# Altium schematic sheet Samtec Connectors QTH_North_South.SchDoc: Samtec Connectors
size A3; Date: 01-DEC-2013; CompanyName: STMicroelectronics; Organization: Microcontrollers Division; Address1: 12, Rue Jules HOROWITZ; Address2: 38019 Grenoble; Address3: FRANCE; DocumentNumber: MB1263; Revision: C-04; SheetNumber: 6; SheetTotal: 11; Project: STM32MP157-EVAL; PageSetup: Record=PageOptions¦CenterHorizontal=True¦CenterVertical=True¦PrintScale=1.00¦XCorrection=1.00¦YCorrection=1.00¦PrintKind=1¦BorderSize=5000000¦LeftOffset=0¦BottomOffset=0¦Orientation=2¦PaperLength=1000¦PaperWidth=1000¦Scale=100¦PaperSource=7¦PrintQuality=-3¦MediaType=1¦DitherType=10¦PrintScaleMode=1¦PaperKind=A3¦PaperIndex=8
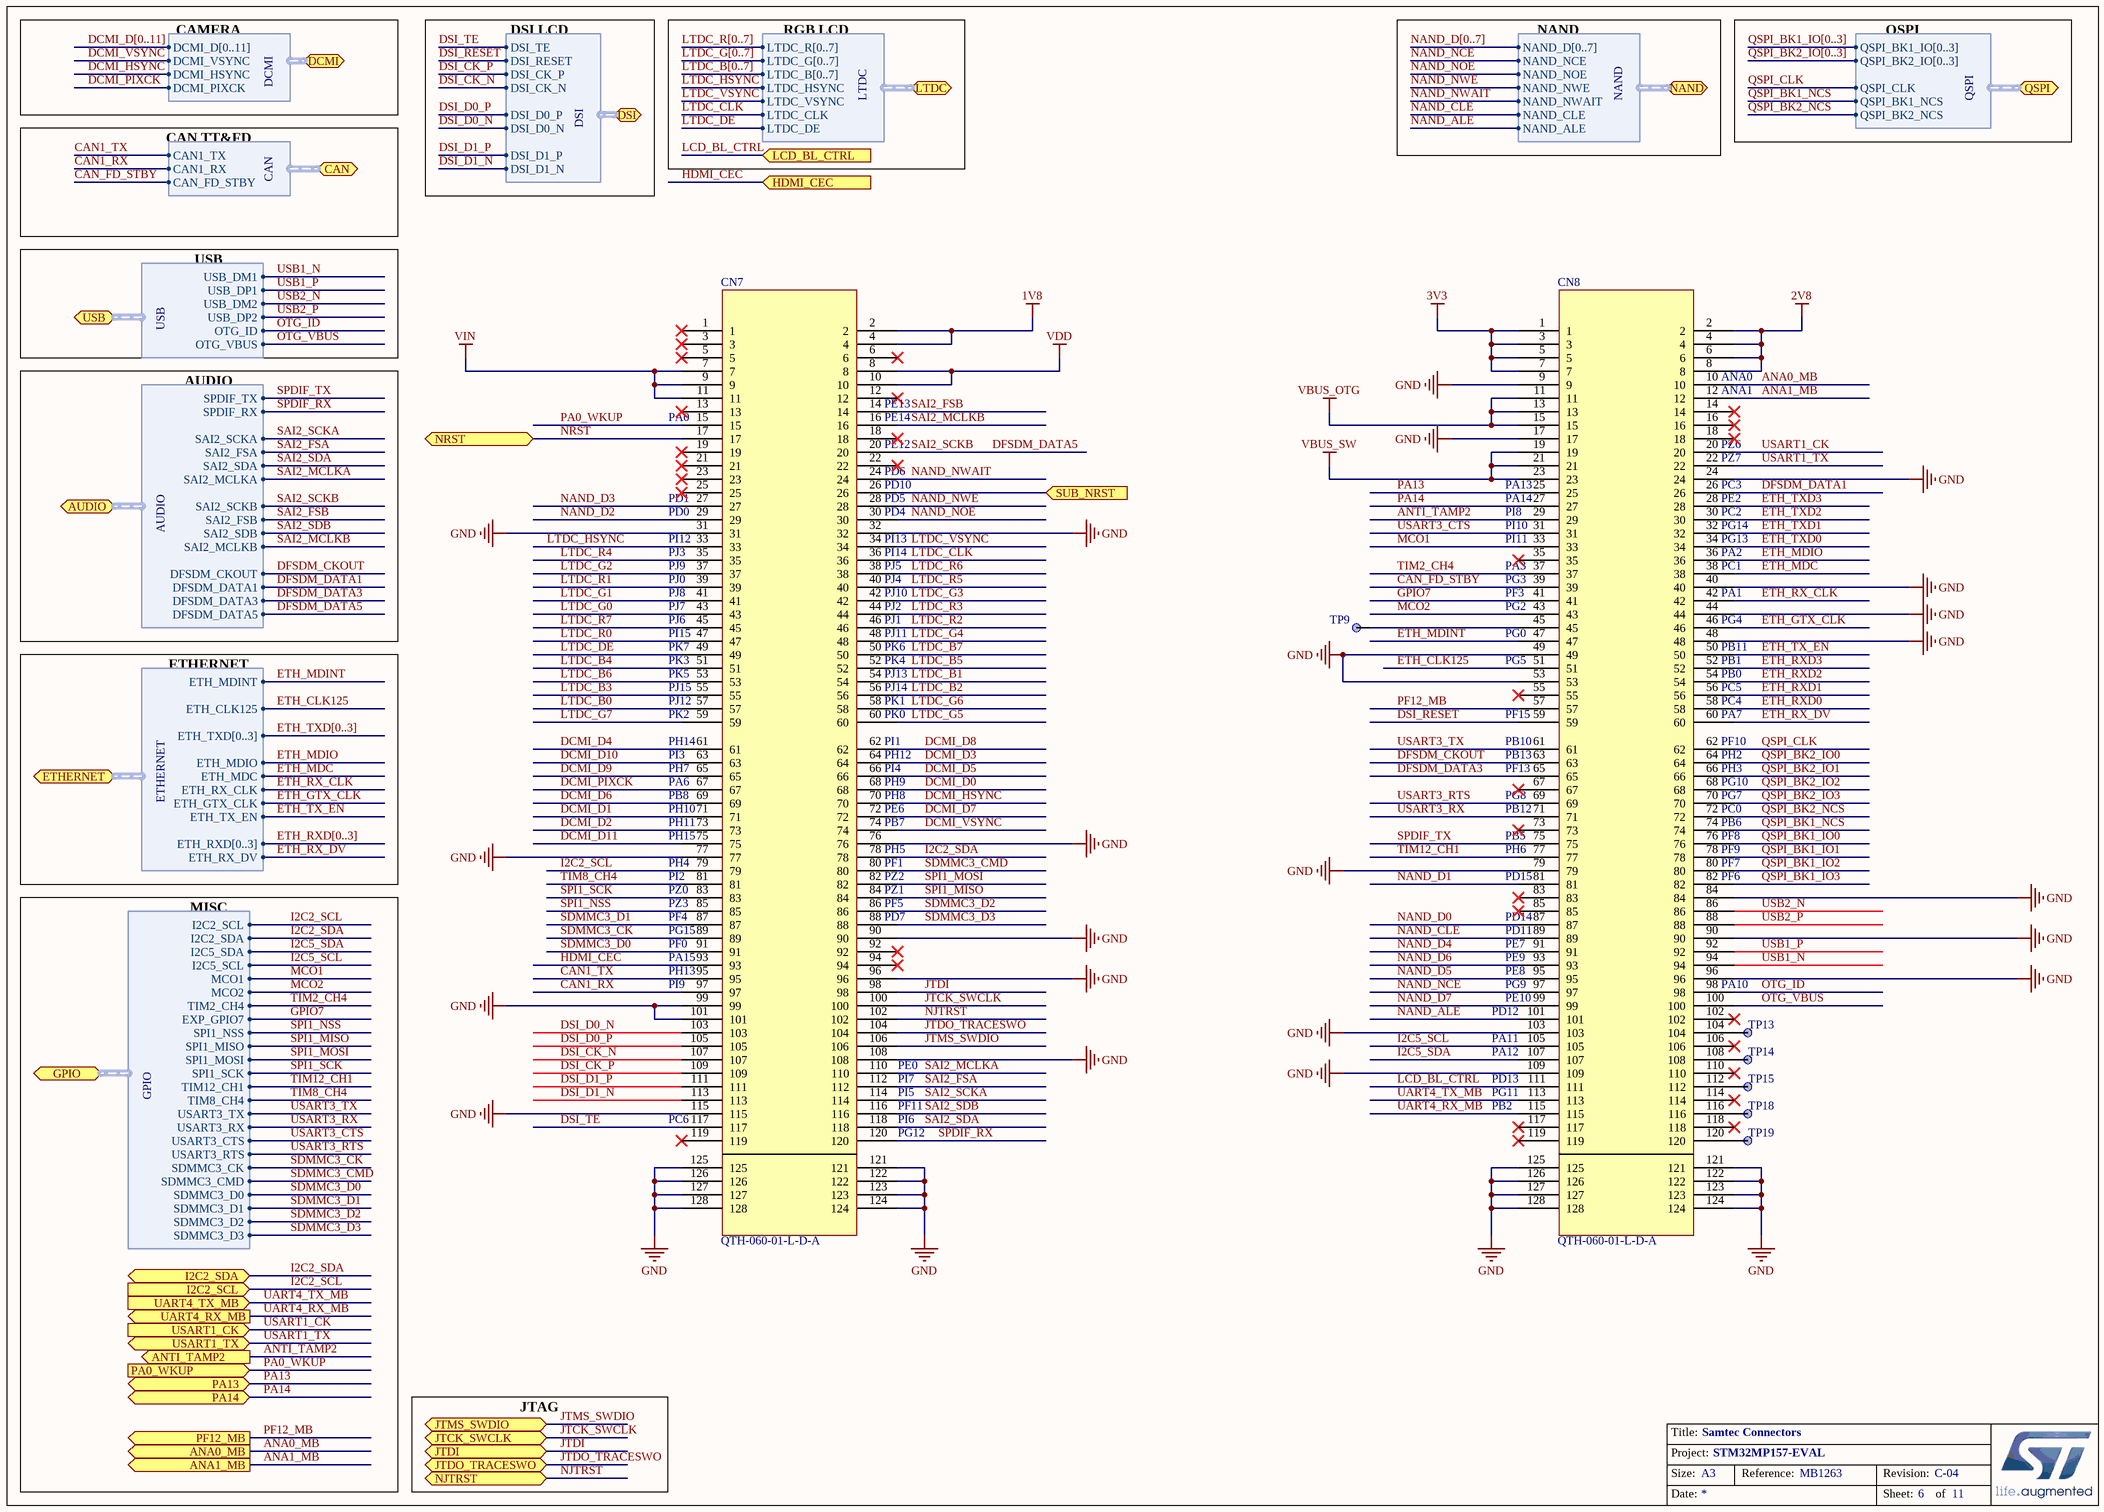
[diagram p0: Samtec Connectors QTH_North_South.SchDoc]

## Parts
CN7  QTH-060-01-L-D-A  [CON_SAMTEC_QTH-060-01-L-D-A]
CN8  QTH-060-01-L-D-A  [CON_SAMTEC_QTH-060-01-L-D-A]
TP9  TP  [TP_SMD_1MM]  (value not drawn)  (no BOM)
TP13  TP  [TP_SMD_1MM]  (value not drawn)  (no BOM)
TP14  TP  [TP_SMD_1MM]  (value not drawn)  (no BOM)
TP15  TP  [TP_SMD_1MM]  (value not drawn)  (no BOM)
TP18  TP  [TP_SMD_1MM]  (value not drawn)  (no BOM)
TP19  TP  [TP_SMD_1MM]  (value not drawn)  (no BOM)

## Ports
ANA0_MB (out), ANA1_MB (out), ANTI_TAMP2 (out), AUDIO (harness AUDIO), CAN (harness CAN), DCMI (harness DCMI), DSI (harness DSI), ETHERNET (harness ETHERNET), GPIO (harness GPIO), HDMI_CEC (in), I2C2_SCL (in), I2C2_SDA (bidir), JTCK_SWCLK, JTDI, JTDO_TRACESWO, JTMS_SWDIO, LCD_BL_CTRL (in), LTDC (harness LTDC), NAND (harness NAND), NJTRST, NRST (bidir), PA0_WKUP (in), PA13, PA14, PF12_MB (out), QSPI (harness QSPI), SUB_NRST (in), UART4_RX_MB (out), UART4_TX_MB (in), USART1_CK (in), USART1_TX (bidir), USB (harness USB)

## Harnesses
NAND: NAND_D[0..7], NAND_NCE, NAND_NOE, NAND_NWE, NAND_NWAIT, NAND_CLE, NAND_ALE
QSPI: QSPI_BK1_IO[0..3], QSPI_BK2_IO[0..3], QSPI_CLK, QSPI_BK1_NCS, QSPI_BK2_NCS
DSI: DSI_CK_P, DSI_CK_N, DSI_D0_P, DSI_D0_N, DSI_D1_P, DSI_D1_N, DSI_TE, DSI_RESET
LTDC: LTDC_R[0..7], LTDC_G[0..7], LTDC_B[0..7], LTDC_HSYNC, LTDC_VSYNC, LTDC_CLK, LTDC_DE
ETHERNET: ETH_MDINT, ETH_CLK125, ETH_TXD[0..3], ETH_MDIO, ETH_MDC, ETH_RX_CLK, ETH_GTX_CLK, ETH_TX_EN, ETH_RXD[0..3], ETH_RX_DV
USB: USB_DM1, USB_DP1, USB_DM2, USB_DP2, OTG_ID, OTG_VBUS
DCMI: DCMI_D[0..11], DCMI_VSYNC, DCMI_HSYNC, DCMI_PIXCK
CAN: CAN1_TX, CAN1_RX, CAN_FD_STBY
GPIO: I2C2_SCL, I2C2_SDA, I2C5_SDA, MCO1, MCO2, TIM2_CH4, EXP_GPIO7, SPI1_NSS, SPI1_MISO, SPI1_MOSI, SPI1_SCK, TIM12_CH1, TIM8_CH4, USART3_TX, USART3_RX, USART3_CTS, USART3_RTS, SDMMC3_CK, SDMMC3_CMD, SDMMC3_D0, SDMMC3_D1, SDMMC3_D2, SDMMC3_D3, I2C5_SCL
AUDIO: SPDIF_TX, SPDIF_RX, SAI2_SCKA, SAI2_FSA, SAI2_SDA, SAI2_SDB, SAI2_MCLKA, DFSDM_CKOUT, DFSDM_DATA1, DFSDM_DATA3, DFSDM_DATA5, SAI2_SCKB, SAI2_FSB, SAI2_MCLKB

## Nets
1V8: CN7.2 CN7.4
2V8: CN8.2 CN8.4 CN8.6 CN8.8
3V3: CN8.1 CN8.3 CN8.5 CN8.7
GND: CN7.31 CN7.32 CN7.76 CN7.77 CN7.90 CN7.96 CN7.99 CN7.101 CN7.108 CN7.115 CN7.121 CN7.122 CN7.123 CN7.124 CN7.125 CN7.126 CN7.127 CN7.128 CN8.9 CN8.17 CN8.24 CN8.40 CN8.44 CN8.48 CN8.49 CN8.53 CN8.79 CN8.84 CN8.90 CN8.96 CN8.103 CN8.109 CN8.121 CN8.122 CN8.123 CN8.124 CN8.125 CN8.126 CN8.127 CN8.128
VBUS_OTG: CN8.11 CN8.13 CN8.15
VBUS_SW: CN8.19 CN8.21 CN8.23
VDD: CN7.8 CN7.10
VIN: CN7.7 CN7.9 CN7.11
ANA0_MB: CN8.10 ; port ANA0_MB
ANA1_MB: CN8.12 ; port ANA1_MB
ANTI_TAMP2: CN8.29 ; port ANTI_TAMP2
CAN1_RX: CN7.97 ; port CAN.CAN1_RX
CAN1_TX: CN7.95 ; port CAN.CAN1_TX
CAN_FD_STBY: CN8.39 ; port CAN.CAN_FD_STBY
DCMI_D0: CN7.68
DCMI_D1: CN7.71
DCMI_D2: CN7.73
DCMI_D3: CN7.64
DCMI_D4: CN7.61
DCMI_D5: CN7.66
DCMI_D6: CN7.69
DCMI_D7: CN7.72
DCMI_D8: CN7.62
DCMI_D9: CN7.65
DCMI_D10: CN7.63
DCMI_D11: CN7.75
DCMI_HSYNC: CN7.70 ; port DCMI.DCMI_HSYNC
DCMI_PIXCK: CN7.67 ; port DCMI.DCMI_PIXCK
DCMI_VSYNC: CN7.74 ; port DCMI.DCMI_VSYNC
DFSDM_CKOUT: CN8.63 ; port AUDIO.DFSDM_CKOUT
DFSDM_DATA1: CN8.26 ; port AUDIO.DFSDM_DATA1
DFSDM_DATA3: CN8.65 ; port AUDIO.DFSDM_DATA3
DFSDM_DATA5: CN7.20 ; port AUDIO.DFSDM_DATA5, port AUDIO.SAI2_SCKB  [also labelled SAI2_SCKB]
DSI_CK_N: CN7.107 ; port DSI.DSI_CK_N
DSI_CK_P: CN7.109 ; port DSI.DSI_CK_P
DSI_D0_N: CN7.103 ; port DSI.DSI_D0_N
DSI_D0_P: CN7.105 ; port DSI.DSI_D0_P
DSI_D1_N: CN7.113 ; port DSI.DSI_D1_N
DSI_D1_P: CN7.111 ; port DSI.DSI_D1_P
DSI_RESET: CN8.59 ; port DSI.DSI_RESET
DSI_TE: CN7.117 ; port DSI.DSI_TE
ETH_CLK125: CN8.51 ; port ETHERNET.ETH_CLK125
ETH_GTX_CLK: CN8.46 ; port ETHERNET.ETH_GTX_CLK
ETH_MDC: CN8.38 ; port ETHERNET.ETH_MDC
ETH_MDINT: CN8.47 ; port ETHERNET.ETH_MDINT
ETH_MDIO: CN8.36 ; port ETHERNET.ETH_MDIO
ETH_RX_CLK: CN8.42 ; port ETHERNET.ETH_RX_CLK
ETH_RX_DV: CN8.60 ; port ETHERNET.ETH_RX_DV
ETH_RXD0: CN8.58
ETH_RXD1: CN8.56
ETH_RXD2: CN8.54
ETH_RXD3: CN8.52
ETH_TX_EN: CN8.50 ; port ETHERNET.ETH_TX_EN
ETH_TXD0: CN8.34
ETH_TXD1: CN8.32
ETH_TXD2: CN8.30
ETH_TXD3: CN8.28
GPIO7: CN8.41 ; port GPIO.EXP_GPIO7
HDMI_CEC: CN7.93 ; port HDMI_CEC
I2C2_SCL: CN7.79 ; port I2C2_SCL, port GPIO.I2C2_SCL
I2C2_SDA: CN7.78 ; port I2C2_SDA, port GPIO.I2C2_SDA
I2C5_SCL: CN8.105 ; port GPIO.I2C5_SCL
I2C5_SDA: CN8.107 ; port GPIO.I2C5_SDA
JTCK_SWCLK: CN7.100 ; port JTCK_SWCLK
JTDI: CN7.98 ; port JTDI
JTDO_TRACESWO: CN7.104 ; port JTDO_TRACESWO
JTMS_SWDIO: CN7.106 ; port JTMS_SWDIO
LCD_BL_CTRL: CN8.111 ; port LCD_BL_CTRL
LTDC_B0: CN7.57
LTDC_B1: CN7.54
LTDC_B2: CN7.56
LTDC_B3: CN7.55
LTDC_B4: CN7.51
LTDC_B5: CN7.52
LTDC_B6: CN7.53
LTDC_B7: CN7.50
LTDC_CLK: CN7.36 ; port LTDC.LTDC_CLK
LTDC_DE: CN7.49 ; port LTDC.LTDC_DE
LTDC_G0: CN7.43
LTDC_G1: CN7.41
LTDC_G2: CN7.37
LTDC_G3: CN7.42
LTDC_G4: CN7.48
LTDC_G5: CN7.60
LTDC_G6: CN7.58
LTDC_G7: CN7.59
LTDC_HSYNC: CN7.33 ; port LTDC.LTDC_HSYNC
LTDC_R0: CN7.47
LTDC_R1: CN7.39
LTDC_R2: CN7.46
LTDC_R3: CN7.44
LTDC_R4: CN7.35
LTDC_R5: CN7.40
LTDC_R6: CN7.38
LTDC_R7: CN7.45
LTDC_VSYNC: CN7.34 ; port LTDC.LTDC_VSYNC
MCO1: CN8.33 ; port GPIO.MCO1
MCO2: CN8.43 ; port GPIO.MCO2
NAND_ALE: CN8.101 ; port NAND.NAND_ALE
NAND_CLE: CN8.89 ; port NAND.NAND_CLE
NAND_D0: CN8.87
NAND_D1: CN8.81
NAND_D2: CN7.29
NAND_D3: CN7.27
NAND_D4: CN8.91
NAND_D5: CN8.95
NAND_D6: CN8.93
NAND_D7: CN8.99
NAND_NCE: CN8.97 ; port NAND.NAND_NCE
NAND_NOE: CN7.30 ; port NAND.NAND_NOE
NAND_NWAIT: CN7.24 ; port NAND.NAND_NWAIT
NAND_NWE: CN7.28 ; port NAND.NAND_NWE
NJTRST: CN7.102 ; port NJTRST
NRST: CN7.17 ; port NRST
OTG_ID: CN8.98 ; port USB.OTG_ID
OTG_VBUS: CN8.100 ; port USB.OTG_VBUS
PA0_WKUP: CN7.15 ; port PA0_WKUP
PA13: CN8.25 ; port PA13
PA14: CN8.27 ; port PA14
PF12_MB: CN8.57 ; port PF12_MB
QSPI_BK1_IO0: CN8.76
QSPI_BK1_IO1: CN8.78
QSPI_BK1_IO2: CN8.80
QSPI_BK1_IO3: CN8.82
QSPI_BK1_NCS: CN8.74 ; port QSPI.QSPI_BK1_NCS
QSPI_BK2_IO0: CN8.64
QSPI_BK2_IO1: CN8.66
QSPI_BK2_IO2: CN8.68
QSPI_BK2_IO3: CN8.70
QSPI_BK2_NCS: CN8.72 ; port QSPI.QSPI_BK2_NCS
QSPI_CLK: CN8.62 ; port QSPI.QSPI_CLK
SAI2_FSA: CN7.112 ; port AUDIO.SAI2_FSA
SAI2_FSB: CN7.14 ; port AUDIO.SAI2_FSB
SAI2_MCLKA: CN7.110 ; port AUDIO.SAI2_MCLKA
SAI2_MCLKB: CN7.16 ; port AUDIO.SAI2_MCLKB
SAI2_SCKA: CN7.114 ; port AUDIO.SAI2_SCKA
SAI2_SDA: CN7.118 ; port AUDIO.SAI2_SDA
SAI2_SDB: CN7.116 ; port AUDIO.SAI2_SDB
SDMMC3_CK: CN7.89 ; port GPIO.SDMMC3_CK
SDMMC3_CMD: CN7.80 ; port GPIO.SDMMC3_CMD
SDMMC3_D0: CN7.91 ; port GPIO.SDMMC3_D0
SDMMC3_D1: CN7.87 ; port GPIO.SDMMC3_D1
SDMMC3_D2: CN7.86 ; port GPIO.SDMMC3_D2
SDMMC3_D3: CN7.88 ; port GPIO.SDMMC3_D3
SPDIF_RX: CN7.120 ; port AUDIO.SPDIF_RX
SPDIF_TX: CN8.75 ; port AUDIO.SPDIF_TX
SPI1_MISO: CN7.84 ; port GPIO.SPI1_MISO
SPI1_MOSI: CN7.82 ; port GPIO.SPI1_MOSI
SPI1_NSS: CN7.85 ; port GPIO.SPI1_NSS
SPI1_SCK: CN7.83 ; port GPIO.SPI1_SCK
SUB_NRST: CN7.26 ; port SUB_NRST
TIM2_CH4: CN8.37 ; port GPIO.TIM2_CH4
TIM8_CH4: CN7.81 ; port GPIO.TIM8_CH4
TIM12_CH1: CN8.77 ; port GPIO.TIM12_CH1
UART4_RX_MB: CN8.115 ; port UART4_RX_MB
UART4_TX_MB: CN8.113 ; port UART4_TX_MB
USART1_CK: CN8.20 ; port USART1_CK
USART1_TX: CN8.22 ; port USART1_TX
USART3_CTS: CN8.31 ; port GPIO.USART3_CTS
USART3_RTS: CN8.69 ; port GPIO.USART3_RTS
USART3_RX: CN8.71 ; port GPIO.USART3_RX
USART3_TX: CN8.61 ; port GPIO.USART3_TX
USB1_N: CN8.94 ; port USB.USB_DM1
USB1_P: CN8.92 ; port USB.USB_DP1
USB2_N: CN8.86 ; port USB.USB_DM2
USB2_P: CN8.88 ; port USB.USB_DP2
NetCN8_45: CN8.45 TP9.1
NetCN8_104: CN8.104 TP13.1
NetCN8_108: CN8.108 TP14.1
NetCN8_112: CN8.112 TP15.1
NetCN8_116: CN8.116 TP18.1
NetCN8_120: CN8.120 TP19.1

Not connected (* = marked no-connect by the designer): CN7 1* 3* 5* 6* 12* 13* 18* 19* 21* 22* 23* 25* 92* 94* 119*; CN8 14* 16* 18* 35* 55* 67* 73* 83* 85* 102* 106* 110* 114* 117* 118* 119*

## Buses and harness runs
bus DCMI_D[0..11]
bus ETH_RXD[0..3]
bus ETH_TXD[0..3]
bus LTDC_B[0..7]
bus LTDC_G[0..7]
bus LTDC_R[0..7]
bus NAND_D[0..7]
bus QSPI_BK1_IO[0..3]
bus QSPI_BK2_IO[0..3]

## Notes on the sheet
- CAMERA
- RGB LCD
- NAND
- QSPI
- CAN TT&FD
- DSI LCD
- USB
- (near CN8) ANA0
- (near CN7) PA0
- (near CN7) PE12
- (near CN7) PE13
- (near CN7) PE14
- (near CN8) PZ6
- (near CN8) ANA1
- (near CN7) PD1
- (near CN7) PD0
- (near CN7) PD6
- (near CN7) PD5
- (near CN7) PD4
- (near CN7) PD10
- (near CN8) PI8
- (near CN8) PA13
- (near CN8) PA14
- (near CN8) PC2
- (near CN8) PE2
- (near CN8) PZ7
- (near CN8) PC3
- (near CN7) PI12
- (near CN7) PJ3
- (near CN7) PJ9
- (near CN7) PJ0
- (near CN7) PI13
- (near CN7) PI14
- (near CN7) PJ5
- (near CN7) PJ4
- (near CN8) PI10
- (near CN8) PI11
- (near CN8) PA3
- (near CN8) PG3
- (near CN8) PC1
- (near CN8) PA2
- (near CN8) PG13
- (near CN8) PG14
- AUDIO
- (near CN7) PJ8
- (near CN7) PJ7
- (near CN7) PJ6
- (near CN7) PI15
- (near CN7) PK7
- (near CN7) PJ10
- (near CN7) PJ2
- (near CN7) PJ1
- (near CN7) PJ11
- (near CN7) PK6
- (near CN8) PF3
- (near CN8) PG2
- (near CN8) PG0
- (near CN8) PB11
- (near CN8) PA1
- (near CN8) PG4
- (near CN7) PK3
- (near CN7) PK5
- (near CN7) PJ15
- (near CN7) PJ12
- (near CN7) PK2
- (near CN7) PK4
- (near CN7) PJ13
- (near CN7) PJ14
- (near CN7) PK1
- (near CN7) PK0
- (near CN8) PG5
- (near CN8) PF15
- (near CN8) PA7
- (near CN8) PC4
- (near CN8) PC5
- (near CN8) PB0
- (near CN8) PB1
- (near CN7) PH14
- (near CN7) PI3
- (near CN7) PH7
- (near CN7) PA6
- (near CN7) PI1
- (near CN7) PH12
- (near CN7) PI4
- (near CN7) PH9
- (near CN8) PB10
- (near CN8) PB13
- (near CN8) PF13
- (near CN8) PG10
- (near CN8) PH3
- (near CN8) PH2
- (near CN8) PF10
- (near CN7) PB8
- (near CN7) PH10
- (near CN7) PH11
- (near CN7) PH15
- (near CN7) PH8
- (near CN7) PE6
- (near CN7) PB7
- (near CN7) PH5
- (near CN8) PG8
- (near CN8) PB12
- (near CN8) PB5
- (near CN8) PH6
- (near CN8) PF8
- (near CN8) PF9
- (near CN8) PB6
- (near CN8) PC0
- (near CN8) PG7
- ETHERNET
- (near CN7) PH4
- (near CN7) PI2
- (near CN7) PZ0
- (near CN7) PZ3
- (near CN7) PF4
- (near CN7) PF1
- (near CN7) PZ2
- (near CN7) PZ1
- (near CN7) PF5
- (near CN7) PD7
- (near CN8) PD15
- (near CN8) PD14
- (near CN8) PF6
- (near CN8) PF7
- (near CN7) PG15
- (near CN7) PF0
- (near CN7) PA15
- (near CN7) PH13
- (near CN7) PI9
- (near CN8) PD11
- (near CN8) PE7
- (near CN8) PE9
- (near CN8) PE8
- (near CN8) PG9
- PA10
- (near CN8) PD12
- (near CN8) PA11
- (near CN8) PA12
- (near CN8) PE10
- (near CN7) PC6
- (near CN7) PE0
- (near CN7) PI7
- (near CN7) PI5
- (near CN7) PF11
- (near CN7) PI6
- (near CN8) PD13
- (near CN8) PG11
- (near CN8) PB2
- (near CN7) PG12
- MISC
- JTAG

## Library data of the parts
CN7 CN8 = QTH-060-01-L-D-A: Samtec connector QTH 120p; Fitted: YES; Ordered_By: Subcon
TP9 TP13-TP15 TP18 TP19 = TP 1mm: Test Point; Fitted: YES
